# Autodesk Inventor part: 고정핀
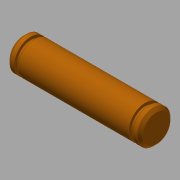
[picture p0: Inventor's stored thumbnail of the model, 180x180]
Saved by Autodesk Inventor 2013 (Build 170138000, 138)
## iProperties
Created: 2015-12
Part Number: 고정핀
Material: 스테인리스강
Document SubType Name: Modeling
Designer: mduedu
Density: 8.08 g/cm^3
Author: mduedu
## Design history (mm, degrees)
sketch "스케치1"
  geometry: C1 r 3 at (0, 0); 1 further point
  constraints: 1 centre point, 1 coincident
  dimensions: "d0" = 6 diameter of C1
extrude "돌출1" new body sketch "스케치1" stored distance "d1" = 24; taper "d2" = 0 deg
chamfer "모따기1" distance "d3" = 0.5; stored, may be unused: second distance "d4" = 2, angle "d5" = 45 deg
sketch "스케치2"
  geometry: L1 (-12, 2.5)-(-11.5, 3) reference; L2 (-11.5, 3)-(11.5, 3) reference; L3 (11.5, 3)-(12, 2.5) reference; L4 (12, 2.5)-(12, -2.5) reference; L5 (12, -2.5)-(11.5, -3) reference; L6 (11.5, -3)-(-11.5, -3) reference; L7 (-11.5, -3)-(-12, -2.5) reference; L8 (-12, -2.5)-(-12, 2.5) reference; L9 (10, 3)-(10.7, 3); L10 (10.7, 3)-(10.7, 2.5); L11 (10.7, 2.5)-(10, 2.5); L12 (10, 2.5)-(10, 3); L13 (0, 0)-(12, 0)
  constraints: 10 end point, 2 parallel, 1 collinear, 1 horizontal, 1 midpoint, 1 perpendicular
  dimensions: "d6" = 10 distance from line of L12 L13.start; "d7" = 5 diameter of L11 L13; "d8" = 0.7 distance of L9.start L9.end
revolve "회전1" sketch "스케치2" stored, may be unused: angle "d9" = 90 deg
node "솔리드1"
mirror "대칭1"
node "절단 모서리 투영1"
